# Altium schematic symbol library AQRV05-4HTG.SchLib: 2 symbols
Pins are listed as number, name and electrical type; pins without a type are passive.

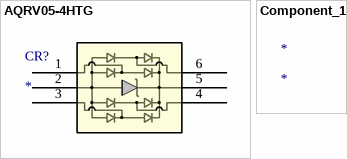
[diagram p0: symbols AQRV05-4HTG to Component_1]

## AQRV05-4HTG
designator CR?
No Description Available; Mfr_Name: Littelfuse Inc
footprint SOT23-6_LTF
pins: 1, 2, 3, 4, 5, 6

## Component_1
designator *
